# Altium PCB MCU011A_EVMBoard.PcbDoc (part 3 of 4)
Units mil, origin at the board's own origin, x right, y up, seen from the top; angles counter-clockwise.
Board outline 10115 x 9285 mil, 4 copper layers (Top Layer, GND, PWR, Bottom Layer), stack 61.2 mil thick; 438 components, 207 nets, 1196 pads, 248 vias.
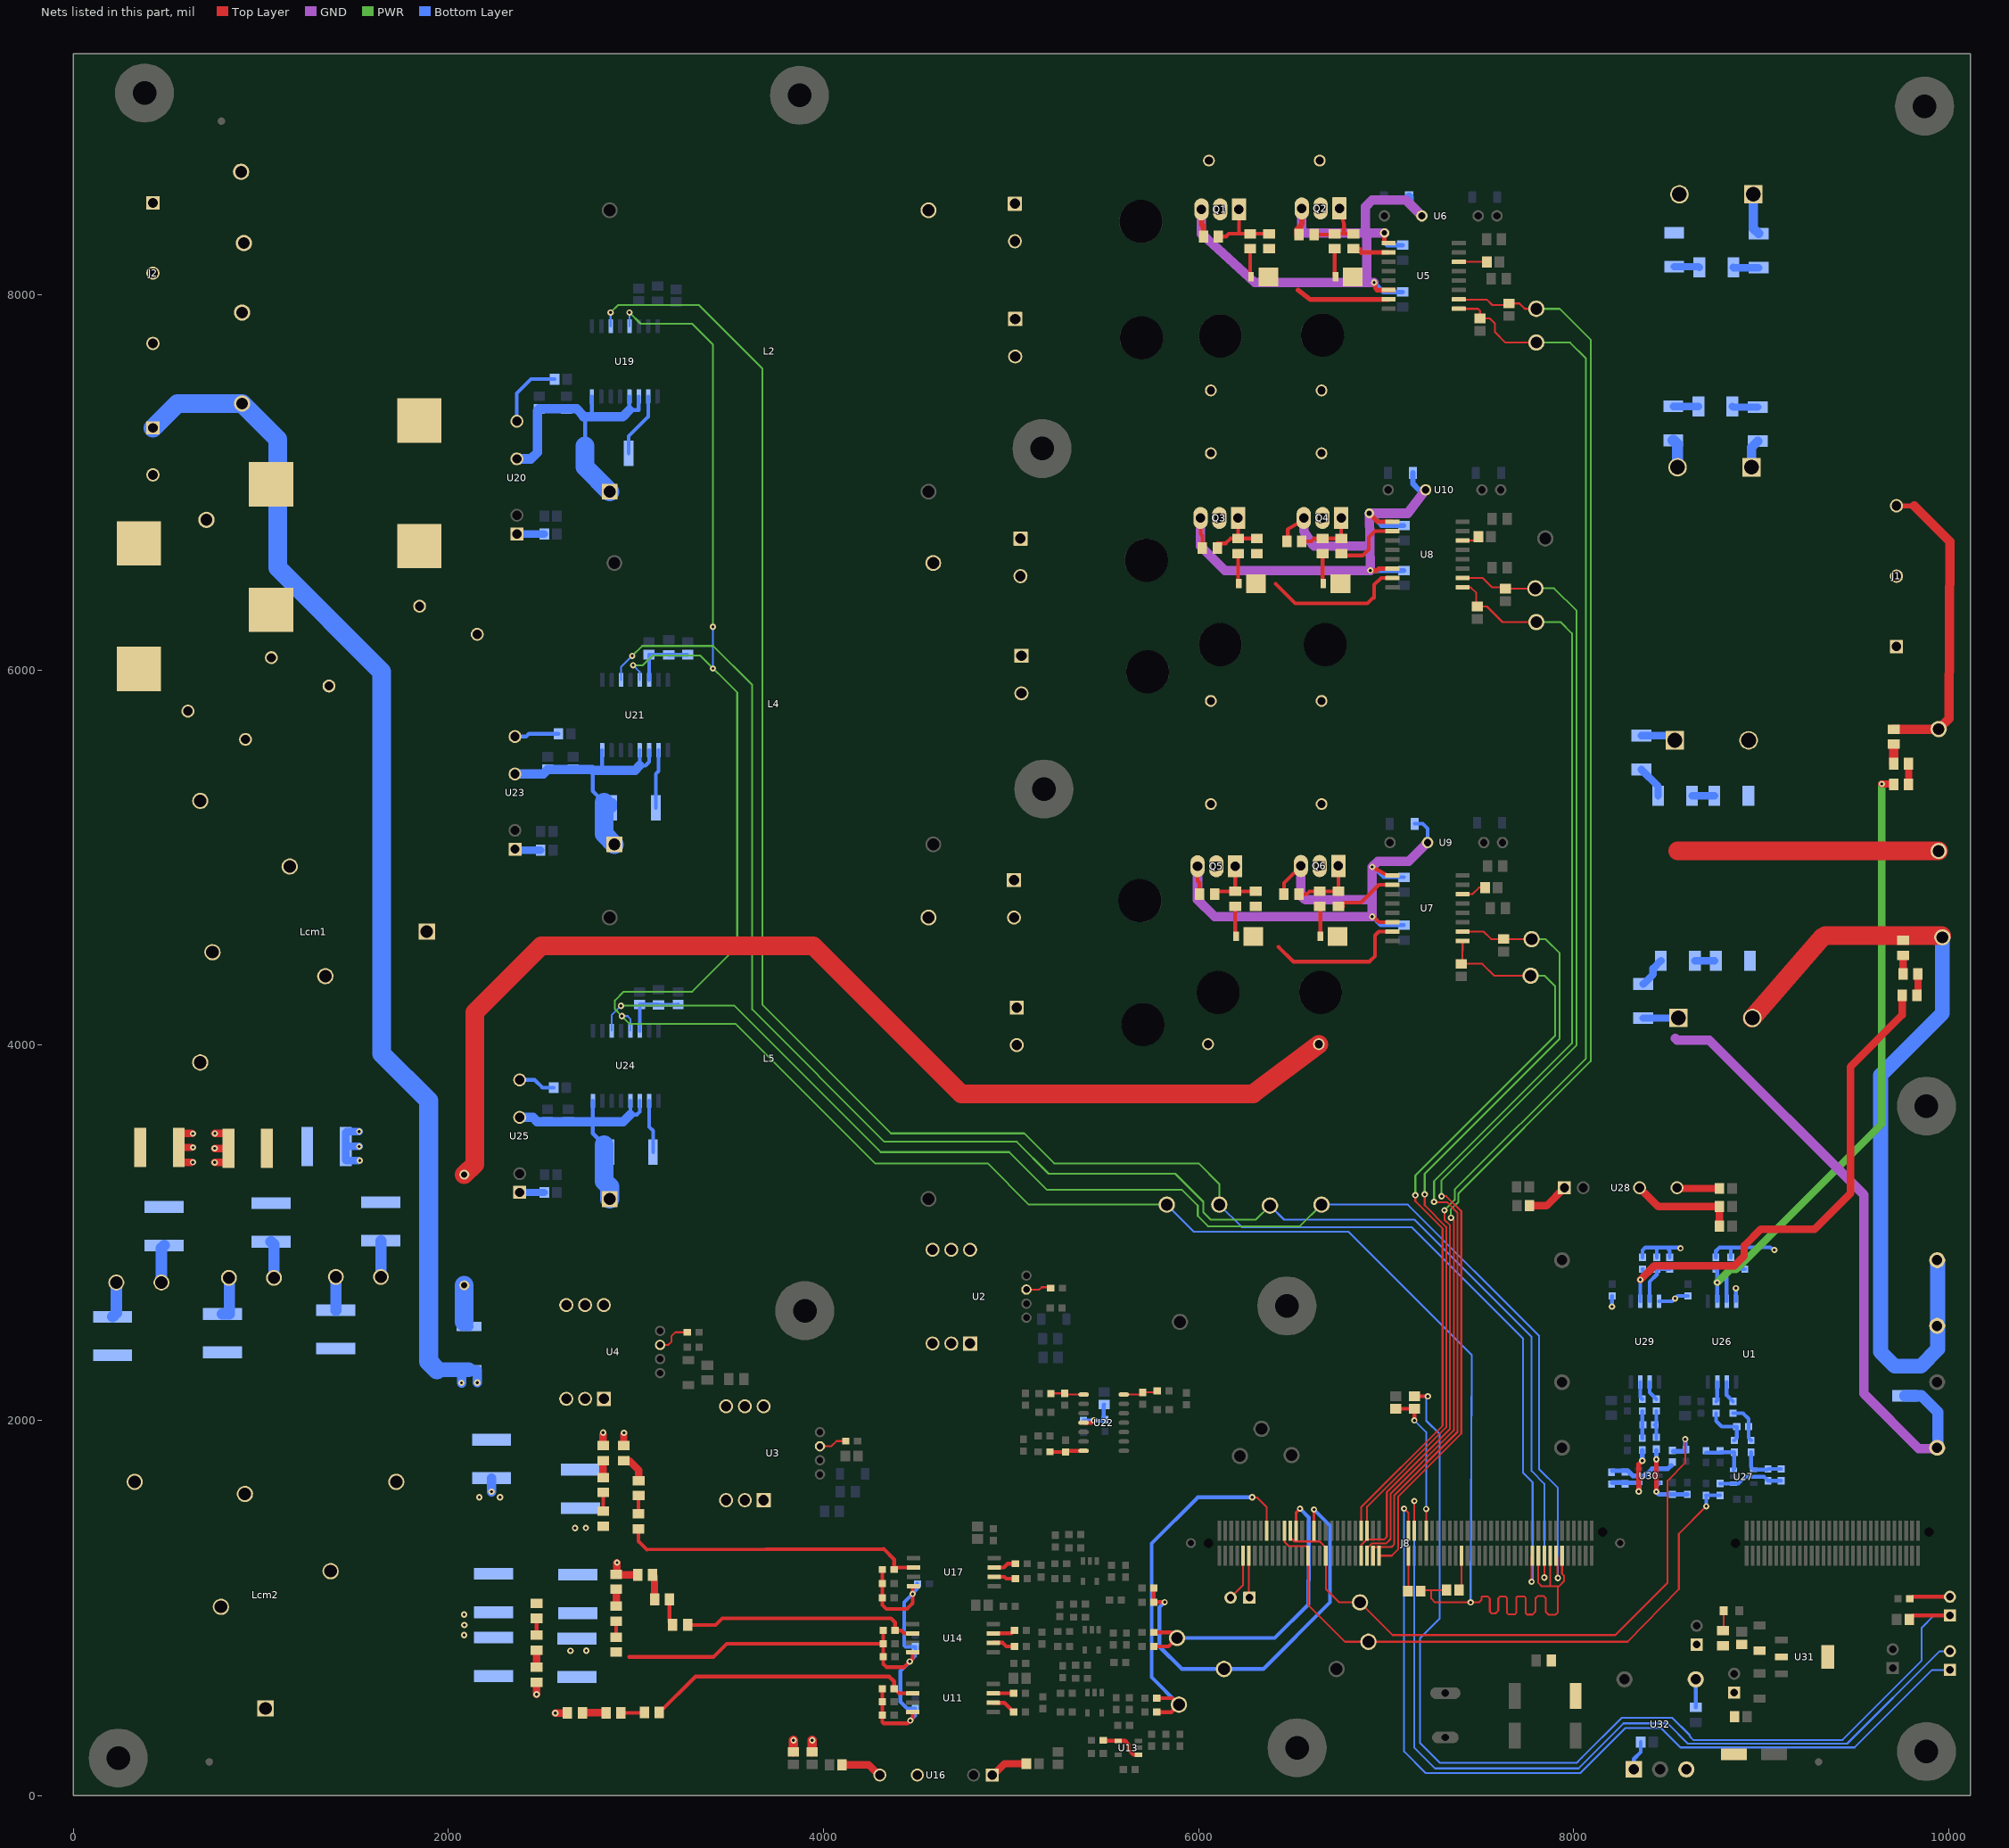
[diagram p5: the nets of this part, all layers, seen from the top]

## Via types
v1: diameter 34, hole 16, Top Layer to Bottom Layer, 243 vias
v2: diameter 50, hole 28, Top Layer to Bottom Layer, 5 vias

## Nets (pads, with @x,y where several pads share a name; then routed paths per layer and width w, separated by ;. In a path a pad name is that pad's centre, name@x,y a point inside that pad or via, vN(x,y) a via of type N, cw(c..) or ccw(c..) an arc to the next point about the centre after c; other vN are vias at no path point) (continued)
NetC67_2: C67.2 C68.1 L12.1 U21.14 | length 336.8
  Bottom Layer w20: U21.14@3070,5946.69 C67.2@3070,6081.54 C68.1@3173.46,6081.54 ; C68.1@3175,6080 L12.1@3273.46,6080
NetC69_2: C69.2 C70.1 L13.1 U22.4 | length 252.5
  Top Layer w20: U22.4@5386.4,1987.74 5428.64,1987.74 v1(5440.45,1999.55)
  Bottom Layer w20: C69.2@5385.96,1999.23 5440.14,1999.23 v1(5440.45,1999.55) 5493.68,1999.55 5493.68,2081.99 L13.1@5495.96,2084.27
NetC76_1: C76.1 C77.2 L16.1 U24.14 | length 343.6
  Bottom Layer w20: U24.14@3020,4077.01 C77.2@3020,4216.54 C76.1@3118.46,4216.54 ; C76.1@3120,4215 3223.46,4215 L16.1@3225,4216.54
NetC82_1: C82.1 R96.1 R99.2 U27.4 | length 246.5
  Bottom Layer w20: R99.2@8945,1830.45 8945,1751.54 U27.4@8959.13,1737.4 9030.9,1737.4 C82.1@9035,1741.5 R96.1@9105,1741.5
NetC82_2: C82.2 R96.2 R101.1 U27.1 | length 349.7
  Bottom Layer w20: R101.1@8780,1663.45 8780.84,1662.6 U27.1@8850.86,1662.6 8877.6,1662.6 8915,1700 9013.51,1700 C82.2@9035,1678.51 R96.2@9105,1678.51
NetC87_1: C87.1 R98.2 R99.1 | length 216.4
  Bottom Layer w20: R98.2@8848.09,2038.27 8901.73,2038.27 8931.5,2008.5 C87.1@8931.5,1966.95 8931.5,1906.95 R99.1@8945,1893.45
NetC87_2: C87.2 R102.2 R103.1 | length 243.3
  Bottom Layer w20: R102.2@8758.09,2038.27 8758.09,1996.91 8788.05,1966.95 C87.2@8868.5,1966.95 8868.5,1906.95 R103.1@8855,1893.45
NetC89_1: C89.1 R103.2 R105.2 U27.3 | length 245.6
  Bottom Layer w20: R105.2@8705,1828.45 8780,1828.45 8782.01,1830.45 R103.2@8855,1830.45 8855,1741.54 U27.3@8850.86,1737.4
NetC90_2: C90.2 R104.1 U26.3 | length 256.2
  Bottom Layer w20: U26.3@8814.41,2634.57 8814.41,2784.21 R104.1@8836.7,2806.5 C90.2@8911.7,2806.5
NetC94_1: C94.1 R108.1 R111.2 U30.4 | length 415.5
  Top Layer w25: v1(8345.86,1620.86) 8345.86,1765.86 v1(8365,1785)
  Bottom Layer w25: R108.1@8205,1668.51 8275,1668.51 8275.9,1667.6 U30.4@8345.86,1667.6 v1(8345.86,1620.86) ; v1(8365,1785) R111.2@8365,1840.45
NetC94_2: C94.2 R108.2 R113.1 U30.1 | length 347.4
  Bottom Layer w25: R108.2@8205,1731.5 8275,1731.5 8287.04,1731.5 8313.53,1705.01 8380.31,1705.01 8417.71,1742.41 U30.1@8454.13,1742.41 8501.96,1742.41 R113.1@8518.9,1759.35
NetC99_1: C99.1 R110.2 R111.1 | length 147
  Bottom Layer w20: R111.1@8365,1903.45 R110.2@8365,2050.45
NetC99_2: C99.2 R114.2 R115.1 | length 154.1
  Bottom Layer w20: R115.1@8440,1903.45 8440,1968.45 C99.2@8431.5,1976.95 8440,1985.45 R114.2@8440,2050.45
NetC101_1: C101.1 R115.2 R117.2 U30.3 | length 444.9
  Top Layer w25: v1(8440,1620) v1@8440,1790
  Bottom Layer w25: v1@8440,1790 R115.2@8440,1840.45 ; U30.3@8454.13,1667.6 8440,1653.47 v1(8440,1620) 8454.55,1605.45 C101.1@8525,1605.45 R117.2@8605,1605.45
  other v1: 8440,1792
NetC102_2: C102.2 R116.1 U29.3 | length 258.2
  Bottom Layer w20: U29.3@8404.41,2634.57 8404.41,2739.41 8443.7,2778.7 R116.1@8443.7,2806.5 ; R116.1@8441.7,2806.5 R116.1@8443.7,2806.5 ; C102.2@8511.7,2806.5 R116.1@8443.7,2806.5
NetC103_2: C103.2 J8.64 R120.2 | length 774.8
  Top Layer w10: J8.64@7212.8,1412.8 v1(7212.8,1527.8)
  Top Layer w20: C103.2@7050,2061.54 R120.2@7150,2061.54 v1(7150,2000)
  Bottom Layer w10: v1(7150,2000) 7212.8,1937.2 v1(7212.8,1527.8)
NetC105_2: C105.2 C106.1 L21.1 U32.1 | length 160.1
  Bottom Layer w20: U32.1@8320,140 8320,195 8356.54,231.54 C105.2@8356.54,285
NetC107_1: C107.1 C108.2 J11.1 U32.3
NetC109_1: C109.1 C110.2 J12.1 R123.2 U31.2 U31.4
NetCm1_1: Cm1.1 Cvn4.2 Cvn5.2 Cvn6.2 RN1.2 | length 301.6
  Bottom Layer w50: RN1.2@2085,2526.14 RN1.2@2110,2501.14 ; v1(2230,1620) Cvn4.2@2230,1692.64
  Bottom Layer w100: RN1.2@2085,2526.14 Cm1.1@2085,2719.72
  other v1: 2084,856 2085,909 2084,965 2165,1590 2275,1590
NetCx1_1: Cx1.1 Lcm2.6 Ldm3.2 | length 190.9
  Bottom Layer w60: Cx1.1@210,2552.36 229.92,2572.28 Ldm3.2@229.92,2735
NetCx1_2: Cx1.2 Cx2.2 Cx3.2
NetCx2_1: Cx2.1 Lcm2.4 Ldm2.2 | length 231
  Bottom Layer w60: Cx2.1@795,2567.36 832.36,2567.36 832.36,2757.56 Ldm2.2@829.92,2760
NetCx3_1: Cx3.1 Lcm2.2 Ldm1.2 | length 177.7
  Bottom Layer w60: Ldm1.2@1399.92,2765 1400,2764.92 Cx3.1@1400,2587.36
NetCx4_1: Cx4.1 Cy1.1 Lcm1.5 Ldm3.1 | length 203.8
  Bottom Layer w60: Ldm3.1@470.08,2735 470.08,2917.72 Cx4.1@485,2932.64
NetCx4_2: Cx4.2 Cx5.2 Cx6.2
NetCx5_1: Cx5.1 Cy2.1 Lcm1.3 Ldm2.1 | length 198.9
  Bottom Layer w60: Cx5.1@1055,2952.64 1070.08,2937.56 Ldm2.1@1070.08,2760
NetCx6_1: Cx6.1 Cy3.1 Lcm1.1 Ldm1.1 | length 555.7
  Bottom Layer w40: v1@1520,3385 1454.72,3385 1452.36,3387.36 Cy3.1@1452.36,3460 ; v1(1525,3460) Cy3.1@1452.36,3460 ; v1(1525,3540) 1458.27,3540 1452.36,3534.09 Cy3.1@1452.36,3460
  Bottom Layer w60: Cx6.1@1640,2957.64 1640,2765.08 Ldm1.1@1640.08,2765
  other v1: 1528,3385
NetD1_2: D1.2 D4.1 L2.3 Q1.2
NetD2_2: D2.2 D5.1 L4.3 Q3.2
NetD3_2: D3.2 D6.1 L5.3 Q5.2
NetD7_1: D7.1 R20.1 U5.15 | length 500
  Top Layer w25: 6530,8025 6595,7975 U5.15@7012.99,7975
NetD7_2: D7.2 R19.2 | length 151.7
  Top Layer w20: R19.2@6275,8245 6275,8099 D7.2@6279,8095
NetD8_1: D8.1 R26.1 U5.10 | length 182
  Top Layer w20: R26.1@6825,8245 6860,8245
  Top Layer w25: 6866,8224 U5.10@7012.99,8225
NetD8_2: D8.2 R25.2 | length 151.7
  Top Layer w20: R25.2@6725,8245 6725,8099 D8.2@6729,8095
NetD9_1: D9.1 R29.1 U7.15 | length 765.9
  Top Layer w20: 6425,4525 6505,4445 6910,4445 6940,4475 6940,4585 6960,4605 U7.15@7027.01,4605
NetD9_2: D9.2 R28.2 | length 161.7
  Top Layer w20: R28.2@6195,4740 6195,4584 D9.2@6199,4580
NetD10_1: D10.1 R35.1 U8.15 | length 744.6
  Top Layer w20: 6410,6460 6515,6355 6900,6355 6930,6385 ; 6935,6385 6935,6450 ; 6935,6455 6972.99,6490 U8.15@7025,6490
NetD10_2: D10.2 R34.2 | length 162.1
  Top Layer w20: R34.2@6210,6620.39 6210,6464 D10.2@6214,6460
NetD11_1: D11.1 R38.1 U7.10 | length 319.4
  Top Layer w20: R38.1@6745,4740 R38.1@6770,4740 ; R38.1@6775,4760 6865,4760 6960,4855 U7.10@7030,4855
NetD11_2: D11.2 R36.2 | length 161.7
  Top Layer w20: R36.2@6645,4740 6649,4736 D11.2@6649,4580
NetD12_1: D12.1 R44.1 U8.10 | length 343.4
  Top Layer w20: R44.1@6760,6620.39 R44.1@6771.75,6620.39 ; R44.1@6765,6610 6824.99,6610.67 6875.67,6610.67 6906.96,6641.96 6906.96,6706.96 6940,6740 U8.10@7005,6740
NetD12_2: D12.2 R43.2 | length 161.9
  Top Layer w20: R43.2@6660.39,6620.39 6660.39,6463.61 D12.2@6664,6460
NetD13_2: D13.2 R123.1 | length 106.5
  Top Layer w10: R123.1@8795,879.68 8798.66,883.35 D13.2@8798.66,984.68
NetJ5_1: J5.1 J8.11 | length 225.2
  Top Layer w10: J8.11@6267.91,1278.94 6267.41,1278.43 6267.41,1057.59 J5.1@6270,1055
NetJ5_2: J5.2 J8.9 | length 251.4
  Top Layer w10: J5.2@6170,1055 6236.42,1121.42 J8.9@6236.42,1278.94
NetJ7_1: J7.1 J8.58 | length 4697.6
  Top Layer w10: v1(7095,1530) 7118.31,1506.69 J8.58@7118.31,1412.8
  Bottom Layer w10: v1(7095,1530) 7095,235 7210,120 8035,120 8275,360 8465,360 8568,257 9497,257 9910,670 J7.1@10010,670
NetJ7_2: J7.2 J8.60 | length 4725.8
  Top Layer w10: J8.60@7149.8,1412.8 v1(7149.8,1569.8)
  Bottom Layer w10: v1(7149.8,1569.8) 7149.8,255.2 7260,145 8025,145 8265,385 8500,385 8608,277 9457,277 9950,770 J7.2@10010,770
NetJ8_57: J8.57 R118.1 | length 162.2
  Top Layer w10: R118.1@7118.31,1116.77 J8.57@7118.31,1278.94
NetJ8_75: J8.75 R121.1 | length 168.7
  Top Layer w10: R121.1@7401.77,1110.24 J8.75@7401.77,1278.94
NetJ9_1: J9.1 R119.1 R120.1 | length 5610.5
  Top Layer w20: R120.1@7150,2128.46 v1@7213.46,2128.46 ; R119.1@9788.46,940 9808.46,960 J9.1@10005,960
  Bottom Layer w10: v1(7222,2128) 7214,2120 7214,2101 7213.46,1997.96 7285,1926.42 7285,945 7180,840 7180,280 7285,175 8015.25,175 8042,201.75 8042,202 8255,415 8525,415 8618,322 8618,315.75 8636.75,297 9432,297 9855,720 9855,895 9920,960 J9.1@10005,960
NetJ9_2: J9.2 R122.2 | length 209.1
  Top Layer w20: R122.2@9800,1050 9810,1060 J9.2@10005,1060
NetL7_2: L7.2 U16.1 | length 208.5
  Top Layer w40: U16.1@4900,105 4965,170 L7.2@5081.54,170
NetL8_1: L8.1 U16.7 | length 226.4
  Top Layer w40: L8.1@4098.46,165 4240,165 U16.7@4300,105
NetL10_2: L10.2 U20.1 | length 146.5
  Bottom Layer w40: U20.1@2365,6725 L10.2@2511.54,6725
NetL11_1: L11.1 U20.7 | length 382.6
  Bottom Layer w20: U20.7@2365,7325 2365,7475 2440,7550 L11.1@2566.54,7550
NetL14_2: L14.2 U23.1 | length 138.6
  Bottom Layer w40: U23.1@2355,5045 2360,5040 L14.2@2491.54,5040
NetL15_1: L15.1 U23.7 | length 237.7
  Bottom Layer w20: U23.7@2355,5645 2415,5645 2430,5660 L15.1@2586.54,5660
NetL17_2: L17.2 U25.1 | length 131.5
  Bottom Layer w40: U25.1@2380,3215 L17.2@2511.54,3215
NetL18_1: L18.1 U25.7 | length 198.8
  Bottom Layer w20: U25.7@2380,3815 2460,3815 2501.54,3773.46 L18.1@2561.59,3773.46
NetL19_2: L19.2 U28.1 | length 226.1
  Top Layer w40: L19.2@7763.46,3144.37 7854.37,3144.37 U28.1@7950,3240
NetL20_1: L20.1 U28.7 | length 228
  Top Layer w40: U28.7@8550,3240 8553.52,3236.48 L20.1@8776.54,3236.48
NetLcm1_2: Lcm1.2 RT1.2
NetLcm1_4: Lcm1.4 RT2.2
NetLcm1_6: Lcm1.6 RT3.2
NetR1_1: R1.1 U2.9 | length 138.3
  Top Layer w10: U2.9@5083.72,2695 U2.9@5081.54,2697.19 5149.98,2697.19 5162.8,2710 5204.33,2710 R1.1@5209.33,2705
NetR3_1: R3.1 R5.2 | length 136.1
  Bottom Layer w40: R5.2@8845.55,7404.68 8849.45,7400.79 R3.1@8980,7400.79
NetR4_1: R4.1 R6.2 | length 134.7
  Bottom Layer w40: R6.2@8850.55,8145 8851.1,8144.45 R4.1@8985,8144.45
NetR5_1: R5.1 R7.2 | length 134.7
  Bottom Layer w40: R7.2@8530,7405.24 8663.9,7405.24 R5.1@8664.45,7404.68
NetR6_1: R6.1 R8.2 | length 136.3
  Bottom Layer w40: R8.2@8535,8149.45 8665,8149.45 R6.1@8669.45,8145
NetR9_1: R9.1 U3.9 | length 149.2
  Top Layer w10: U3.9@3980.83,1862.18 4042.19,1862.18 4070,1890 R9.1@4118.5,1890
NetR11_1: R11.1 R13.2 | length 163.3
  Bottom Layer w40: R11.1@8370,4325.55 8422.56,4378.11 8422.56,4408.66 R13.2@8463.9,4450
NetR12_1: R12.1 R14.2 | length 176.5
  Bottom Layer w40: R12.1@8360,5469.45 8449.45,5380 R14.2@8449.45,5330
NetR13_1: R13.1 R15.2 | length 105.4
  Bottom Layer w40: R13.1@8645,4450 R15.2@8750.36,4449
NetR14_1: R14.1 R16.2 | length 118.9
  Bottom Layer w40: R14.1@8630.55,5330 R16.2@8749.45,5330
NetR17_1: R17.1 U4.9 | length 190.6
  Top Layer w10: U4.9@3128.52,2402.18 3172.18,2402.18 3190,2420 3190,2450 3210,2470 R17.1@3273.5,2470
NetR24_1: R24.1 U5.6 | length 171.5
  Top Layer w10: U5.6@7385.01,8175 7470,8175 7490,8175 R24.1@7556.54,8175
NetR33_1: R33.1 U7.6 | length 134
  Top Layer w10: U7.6@7407.01,4805 7460,4805 7495,4840 R33.1@7526.54,4840
NetR42_1: R42.1 U8.6 | length 99.5
  Top Layer w10: U8.6@7395.47,6690 R42.1@7495,6690
NetR46_1: R46.1 R47.2 | length 125
  Top Layer w40: R46.1@2715,441.46 R47.2@2840,441.46
NetR47_1: R47.1 R49.2 | length 125.6
  Top Layer w20: R47.1@2920,441.46 3043.54,441.46 R49.2@3045,442.91
NetR49_1: R49.1 R52.2 U11.2 | length 1489.8
  Top Layer w20: R49.1@3125,442.91 3317.09,635 4350,635 4376.5,608.5 R52.2@4376.5,570 4401.5,545 U11.2@4475.43,545
NetR50_1: R50.1 U11.6 | length 129.6
  Top Layer w20: U11.6@4904.57,495 4963.5,495 R50.1@5013.5,445
NetR54_1: R54.1 U11.7 | length 108.9
  Top Layer w20: U11.7@4904.57,545 R54.1@5013.5,545
NetR59_1: R59.1 U13.1 U13.4 | length 237.3
  Top Layer w20: R59.1@5491.5,295 5494.09,292.4 U13.4@5570.87,292.4 5607.6,292.4 5625,275 5625,245 5652.4,217.6 U13.1@5679.13,217.6
NetR61_1: R61.1 R62.2 | length 134.1
  Top Layer w40: R61.1@3089,1176.46 3099,1166.46 R62.2@3099,1046.46
NetR62_1: R62.1 R64.2 | length 143.1
  Top Layer w20: R62.1@3179,1046.46 3179,926 R64.2@3195,910
NetR64_1: R64.1 R67.2 U14.2 | length 1273.6
  Top Layer w20: R64.1@3275,910 3425,910 3460,945 4360,945 4381.5,923.5 R67.2@4381.5,880 4415,880 4430,865 U14.2@4475.43,865
NetR65_1: R65.1 U14.6 | length 122.2
  Top Layer w20: U14.6@4904.57,815 4955,815 4975,795 R65.1@5018.5,795
NetR69_1: R69.1 U14.7 | length 120.2
  Top Layer w20: U14.7@4904.57,865 5003.5,865 R69.1@5018.5,880
NetR73_1: R73.1 R74.2 | length 156.5
  Top Layer w40: R73.1@2935,1786 2963,1786 3015,1734 R74.2@3015,1679
NetR74_1: R74.1 R76.2 | length 95
  Top Layer w20: R76.2@3013,1501.45 R74.1@3013,1596.45
NetR76_1: R76.1 R79.2 U17.2 | length 1633.7
  Top Layer w20: R76.1@3013,1421.45 3013,1355.45 3058,1310.45 4320,1315 4376.5,1258.5 R79.2@4376.5,1205 4387.8,1216.3 U17.2@4480.43,1216.3
NetR77_1: R77.1 U17.6 | length 118.1
  Top Layer w20: U17.6@4909.57,1166.3 4965,1166.3 4975,1156.3 R77.1@5023.5,1156.3
NetR81_1: R81.1 U17.7 | length 122.2
  Top Layer w20: U17.7@4909.57,1216.3 4961.3,1216.3 4981.3,1236.3 R81.1@5023.5,1236.3
NetR85_2: R85.2 R87.1 U22.1 | length 177.2
  Top Layer w10: R87.1@5212.46,2142.74 5213.96,2144.23 R85.2@5285.96,2144.23 5292.46,2137.74 U22.1@5386.4,2137.74
NetR86_2: R86.2 R88.1 U22.7 | length 182.2
  Top Layer w20: R88.1@5207.46,1832.74 5208.96,1831.24 R86.2@5290.96,1831.24 5297.46,1837.74 U22.7@5386.4,1837.74
NetR91_2: R91.2 R92.2 U22.14 | length 187.7
  Top Layer w10: U22.14@5600.96,2137.74 5689.47,2137.74 R91.2@5700.96,2149.23 5779,2149.23 R92.2@5782.5,2152.74
NetR94_1: R94.1 R95.2 | length 104
  Top Layer w50: R95.2@9705,5500 R94.1@9705,5604
NetR95_1: R95.1 R97.2 | length 110
  Top Layer w40: R97.2@9785,5390 R95.1@9785,5500
NetR97_1: R97.1 R100.2 U26.2 | length 3284.6
  Top Layer w40: v1(9642,5392) 9703,5392 R97.1@9705,5390
  PWR w40: v1(8764.41,2735) 8833.41,2804 8865,2804 9642,3581 v1(9642,5392)
  Bottom Layer w20: R100.2@8757.29,2806.5 8764.41,2799.39 v1(8764.41,2735) U26.2@8764.41,2634.57 ; R100.2@8764.41,2806.5 R100.2@8764.41,2813.39
NetR98_1: R98.1 U26.6 | length 118.1
  Bottom Layer w20: U26.6@8814.41,2205.43 8814.41,2134.94 R98.1@8848.09,2101.26
NetR102_1: R102.1 U26.7 | length 106.8
  Bottom Layer w20: R102.1@8758.09,2101.26 8764.41,2107.58 U26.7@8764.41,2205.43
NetR106_1: R106.1 R107.2 | length 99
  Top Layer w40: R107.2@9755,4380 R106.1@9755,4479
NetR107_1: R107.1 R109.1 | length 117.1
  Top Layer w40: R109.1@9830,4265 9835,4270 R107.1@9835,4380
NetR109_2: R109.2 R112.2 U29.2 | length 2678
  Top Layer w40: v1(8354.41,2749.41) 8429,2824 8856,2824 8908,2876 8908,2920.43 ; 8910,2932.43 8996.29,3018.71 9283.71,3018.71 9475,3210 9475,3885 9750,4160 R109.2@9750,4265
  Bottom Layer w20: U29.2@8354.41,2634.57 v1(8354.41,2749.41) 8368.7,2763.7 8368.7,2804.5 R112.2@8366.7,2806.5
NetR110_1: R110.1 U29.7 | length 96.4
  Bottom Layer w20: U29.7@8354.41,2205.43 8354.41,2124.04 R110.1@8365,2113.45
NetR114_1: R114.1 U29.6 | length 106.7
  Bottom Layer w20: U29.6@8404.41,2205.43 8404.41,2149.04 R114.1@8440,2113.45
NetR124_2: R124.2 U32.4 | length 150
  Bottom Layer w20: R124.2@8650,470 U32.4@8650,620
NetRT1_1: RT1.1 XF1.1
NetRT2_1: RT2.1 XF2.1
NetRT3_1: RT3.1 XF3.1
NetRvn1_1: Rvn1.1 Rvn4.2 | length 90
  Top Layer w40: Rvn4.2@2825,1696 Rvn1.1@2825,1786
NetRvn2_1: Rvn2.1 Rvn5.2 | length 90
  Top Layer w40: Rvn5.2@2895,1010 Rvn2.1@2895,1100
NetRvn3_1: Rvn3.1 Rvn6.2 | length 90
  Top Layer w40: Rvn3.1@2470,685 Rvn6.2@2470,775
NetRvn4_1: Rvn4.1 Rvn7.2 | length 100
  Top Layer w20: Rvn7.2@2825,1516 Rvn4.1@2825,1616
NetRvn5_1: Rvn5.1 Rvn8.2 | length 85
  Top Layer w20: Rvn8.2@2895,845 Rvn5.1@2895,930
NetRvn6_1: Rvn6.1 Rvn9.2 | length 90
  Top Layer w20: Rvn6.1@2470,855 Rvn9.2@2470,945
NetU2_3: U2.3 U2.5 U2.6
NetU3_3: U3.3 U3.5 U3.6
NetU4_3: U4.3 U4.5 U4.6
PWM1A: J8.49 R22.2 TP1.1 U5.1 | length 7795.3
  Top Layer w10: J8.49@6866.34,1278.94 6866.34,1336.34 6895,1365 6988,1365 7003,1380 7003,1617.85 7340,1954.85 7340,3039.75 7310,3069.75 v1(7310,3120) ; U5.1@7387.01,7925 7490,7925 7500,7915 R22.2@7500,7873.46 7551.54,7873.46 7580,7845 7580,7800 7635,7745 TP1.1@7800,7745
  PWR w10: v1(7310,3120) 7365,3175 7365,3230 8065,3930 8065,7660 7980,7745 TP1.1@7800,7745
PWM1B: J8.51 R23.2 TP2.1 U5.2 | length 7789.4
  Top Layer w10: J8.51@6897.83,1278.94 6897.83,1317.83 6925,1345 7000,1345 7023,1368 7023,1609.57 7360,1946.57 7360,3065 v1(7345,3080) ; U5.2@7414,7974 7536,7974 7565,7945 R23.2@7645,7945 ; R23.2@7655,7953.46 7710,7953.46 7738.46,7925 TP2.1@7800,7925
  PWR w10: v1(7345,3080) 7345,3125 7385,3165 7385,3210 8090,3915 8090,7760 7925,7925 TP2.1@7800,7925
PWM2A: J8.53 R41.2 TP5.1 U8.1 | length 6275.4
  Top Layer w10: J8.53@6929.33,1278.94 6929.33,1310 6944.33,1325 7028,1325 7043,1340 7043,1601.28 7380,1938.28 7380,3106.72 7323.72,3163 7257,3163 v1(7255,3165) ; U8.1@7393.46,6440 7450,6440 7480,6410 R41.2@7480,6345 ; R41.2@7485,6338.46 7536.54,6338.46 7620,6255 TP5.1@7800,6255
  PWR w10: v1(7255,3165) 7255,3275 7990,4010 7990,6195 7930,6255 TP5.1@7800,6255
PWM2B: J8.55 R39.2 TP6.1 U8.2 | length 6253.3
  Top Layer w10: J8.55@6960.83,1278.94 7028.94,1278.94 7063,1313 7063,1593 7400,1930 7400,3115 7320,3195 v1(7295,3195) ; U8.2@7427.01,6490 7515,6490 7565,6440 R39.2@7615,6440 ; R39.2@7635,6433.46 7793.46,6433.46 TP6.1@7795,6435
  PWR w10: v1(7295,3195) 7295,3280 8015,4000 8015,6315 7895,6435 TP6.1@7795,6435
PWM3A: J8.50 R31.2 TP3.1 U7.1 | length 4109.6
  Top Layer w10: J8.50@6866.34,1412.8 6866.34,1537.76 7300,1971.42 7300,3023.18 7155,3168.18 v1(7155,3200) ; R31.2@7400,4433.46 7511.54,4433.46 7575,4370 TP3.1@7770,4370 ; R31.2@7405,4445 U7.1@7407.01,4555
  PWR w10: v1(7155,3200) 7155,3305 7900,4050 7900,4315 7845,4370 TP3.1@7770,4370
PWM3B: J8.52 R32.2 TP4.1 U7.2 | length 4152.6
  Top Layer w10: J8.52@6897.83,1412.8 6897.83,1540.97 7320,1963.14 7320,3031.46 7205,3146.46 v1(7205,3205) ; U7.2@7417.99,4605 7520,4605 7559.14,4565.86 R32.2@7625,4565.86 7774.14,4565.86 TP4.1@7775,4565
  PWR w10: v1(7205,3205) 7205,3315 7925,4035 7925,4490 7850,4565 TP4.1@7775,4565
Q1_GATE: Q1.1 R19.1 R20.2 R21.2 | length 408.3
  Top Layer w20: R21.2@6105,8310 6145,8310 6160,8325 6220,8325 ; Q1.1@6215,8455 6215,8330 6220,8325 ; R20.2@6375,8325 6220,8325
Q1_SOURCE: C8.2 C11.2 C13.2 Q1.3 Q2.3 R21.1 R27.1 U5.9 U5.14 U6.5 | length 3375.6
  Top Layer w25: v1(6935,8065) 6945,8030 ; 6950,8025 U5.14@7012.99,8025 U5.14@7040,8025 ; U5.9@6990,8275 v2(6990,8330)
  Top Layer w30: Q1.3@6015,8455 6015,8377 6025,8367 R21.1@6025,8310 ; R27.1@6535,8345 6550,8381.26 Q2.3@6550,8460
  Top Layer w50: R27.1@6535,8320 R27.1@6535,8345
  GND w50: 6015,8325 Q1.3@6015,8456.84 ; 6020,8320 6300,8065 v1(6935,8065) ; 6550,8330 6890,8330 ; 6550,8345 Q2.3@6550,8461.88 ; 6895,8070 6895,8325 ; v2(6990,8330) 6890,8330 ; U6.5@7190,8420 7105,8505 6925,8505 6890,8470 6890,8330
  Bottom Layer w25: v1(6935,8065) 6986,8014 C8.2@7086.99,8014 ; v2(6990,8330) 6990,8280 7006,8264 C11.2@7086.99,8264
  Bottom Layer w50: C13.2@7121.93,8520 7121.93,8488.07 U6.5@7190,8420
Q2_GATE: Q2.1 R25.1 R26.2 R27.2 | length 350.7
  Top Layer w20: R27.2@6615,8320 6720,8320 R25.1@6725,8325 R26.2@6825,8325 ; Q2.1@6750,8460 6775,8375 6775,8325
Q3_GATE: Q3.1 R34.1 R35.2 R37.2 | length 330.3
  Top Layer w20: R37.2@6100,6675 6144.61,6675 6170,6700.39 R34.1@6210,6700.39 ; Q3.1@6210,6810 R34.1@6210,6700.39 ; R35.2@6310,6700 6309.61,6700.39 R34.1@6210,6700.39
Q3_SOURCE: C17.2 C23.2 C25.2 Q3.3 Q4.3 R37.1 R45.1 U8.9 U8.14 U10.5 | length 3345.6
  Top Layer w20: Q3.3@6010,6810 6025,6795 6010,6780 6010,6725 6020,6715 R37.1@6020,6675 ; R45.1@6475,6680 6475,6750 Q4.3@6560,6800
  Top Layer w25: v2(6910,6835) 6955,6790 U8.9@7032.99,6790 ; v1(6915,6530) 6950,6530 6960,6540 U8.14@7032.99,6540
  GND w50: Q3.3@6010,6810 6010,6660 6140,6530 v1(6915,6530) v2(6910,6835) 7115,6835 U10.5@7210,6960 ; Q4.3@6560,6810 6560,6740 6610,6665 ; 6615,6660 6910,6660
  Bottom Layer w25: v2(6910,6835) 6975,6770 C23.2@7095,6770 ; v1(6915,6530) 7000,6530 C17.2@7095,6530
  Bottom Layer w30: C25.2@7141.93,7050 7141.93,6993.07 7175,6960 U10.5@7210,6960
Q4_GATE: Q4.1 R43.1 R44.2 R45.2 | length 326
  Top Layer w20: R45.2@6550,6685 6600,6685 6615.39,6700.39 R43.1@6660.39,6700.39 R44.2@6760,6700.39 Q4.1@6760,6810
Q5_GATE: Q5.1 R28.1 R29.2 R30.2 | length 359.9
  Top Layer w20: R30.2@6085,4805 6100,4820 R28.1@6195,4820 ; Q5.1@6194,4954 6195,4953 R28.1@6195,4820 ; R29.2@6304.24,4820 R28.1@6195,4820
Q5_SOURCE: C14.2 C20.2 C22.2 Q5.3 Q6.3 R30.1 R40.1 U7.9 U7.14 U9.5 | length 3462.4
  Top Layer w20: Q5.3@5994,4954 6005,4943 5994,4932 5994,4876 5999.87,4870.13 6005,4865 R30.1@6005,4805 ; R40.1@6455,4805 6455,4865 Q6.3@6545,4955 ; v1(6925,4685) 6930,4685 6960,4655 U7.14@7032.99,4655 ; v1(6925,4950) U7.9@7005,4905
  GND w50: Q5.3@5994,4954 5994,4776 6085,4685 v1(6925,4685) 6925,4775 ; Q6.3@6545,4955 6545,4795 6560,4780 ; 6570,4775 6925,4775 ; U9.5@7220,5080 7120,4980 6955,4980 v1(6925,4950) 6925,4775
  Bottom Layer w20: v1(6925,4950) 6930,4950 6985,4895 C20.2@7095,4895 ; C14.2@7095,4640 6975,4640 ; C22.2@7151.93,5180 7195,5180 7220,5155 U9.5@7220,5080 ; 6975,4640 6970,4640 v1(6925,4685) 6930,4685 6975,4640
Q6_GATE: Q6.1 R36.1 R38.2 R40.2 | length 351.2
  Top Layer w20: R40.2@6535,4805 6575,4805 6590,4820 R36.1@6645,4820 R38.2@6745,4820 Q6.1@6745,4955
RSH1_1: RSH1.1 U2.4 U19.2 | length 346
  Bottom Layer w20: RSH1.1@2961.14,7155 2961.14,7246.14 3065,7350 U19.2@3065,7457.99
RSH1_2: C65.2 C66.2 L2.1 RSH1.2 U19.3 U19.4 U19.8 U20.5 | length 1638.8
  Bottom Layer w20: 2720,7350 2728.86,7341.14 RSH1.2@2728.86,7195 ; U19.8@2765,7457.99 2765,7355 2770,7350 ; U19.4@2965,7457.99 2965,7385 3015,7385 U19.3@3015,7457.99
  Bottom Layer w50: U20.5@2365,7125 2440,7125 2475,7160 2475,7381.54 C65.2@2485,7391.54 C66.2@2630,7391.54 2683.46,7391.54 2720,7355 2720,7350 2770,7350 2930,7350 2965,7385
  Bottom Layer w100: RSH1.2@2728.86,7195 RSH1.2@2728.86,7155 2728.86,7081.14 L2.1@2860,6950
RSH2_1: RSH2.1 U3.4 U21.2 | length 313.4
  Bottom Layer w20: RSH2.1@3106.14,5265 3106.14,5446.14 3120,5460 U21.2@3120,5572.68
RSH2_2: C72.2 C73.2 L4.1 RSH2.2 U21.3 U21.4 U21.8 U23.5 | length 1469.9
  Bottom Layer w20: 2770,5465 2770,5355 2830,5295 ; U21.8@2820,5572.68 2820,5470 2825,5465 ; U21.4@3020,5572.68 3020,5490 3050,5490 3070,5510 U21.3@3070,5572.68
  Bottom Layer w50: U23.5@2355,5445 2505,5445 C72.2@2530,5470 C73.2@2665,5470 2765,5470 2770,5465 2825,5465 2995,5465 3020,5490 ; RSH2.2@2873.86,5265 RSH2.2@2873.86,5291.14
  Bottom Layer w100: 2830,5295 2830,5125 L4.1@2885,5070
RSH3_1: RSH3.1 U4.4 U24.2 | length 281.7
  Bottom Layer w20: U24.2@3070,3702.99 3070,3565 3091.14,3543.86 RSH3.1@3091.14,3430
RSH3_2: C80.2 C81.2 L5.1 RSH3.2 U24.3 U24.4 U24.8 U25.5 | length 1384.7
  Bottom Layer w20: U24.8@2770,3702.99 2770,3591.54 2770,3530 2830,3470 ; U24.4@2970,3702.99 2970,3630 3005,3630 3020,3645 U24.3@3020,3702.99
  Bottom Layer w40: 2810,3430 2830,3430 ; L5.1@2858.86,3181.14 L5.1@2860,3180
  Bottom Layer w50: U25.5@2380,3615 2450.25,3615 2473.71,3591.54 C80.2@2528.52,3591.54 C81.2@2638.52,3591.54 2770,3591.54 2931.54,3591.54 2970,3630
  Bottom Layer w100: 2830,3470 2830,3430 2830,3275 2860,3245 L5.1@2860,3180
SD_CLKI: J8.101 J8.105 J8.109 R118.2 R121.2 TP_SD_CLKI1.1 U19.13 U21.13 U24.13 | length 14232.8
  Top Layer w10: R118.2@7170,1095 7183.27,1095 7240,1095 ; R121.2@7320.55,1095 7240,1095 ; J8.101@7811.22,1278.94 7810.72,1278.43 7810.72,1134.28 7829.21,1115.79 7874.21,1115.79 7874.72,1116.29 ; J8.105@7874.21,1278.94 7874.72,1278.43 7874.72,1116.29 ; J8.109@7937.2,1278.94 7937.2,1183.05 7947,1173.25 7947,1142 7920.79,1115.79 7914.98,1115.85 ; 7240,1095 7240,1050 7260,1030 v1(7450,1030) 7494,1030 7509,1045 7509,1058 7513,1062 7540,1062 7552,1050 7552,981 7562,971 7582,971 7597,986 7597,1052 7606,1061 7636,1061 7643,1054 7643,975 7652,966 7685,966 7693,974 7693,1055 7700,1062 7735,1062 7744,1053 7744,972 7751,965 7780,965 7796,981 7796,1052 7807,1063 7840,1063 7851,1052 7851,978 7865,964 7902,964 7914.98,976.98 7914.98,1115.85 ; 7874.72,1116.29 7914.98,1115.85
  PWR w10: v1(2965,7905) 3025,7845 3300,7845 3410,7735 v1(3410,6230) ; v1@2984.75,6025 v1(2985,6025) 3037,6025 3089,6077 3343,6077 3540,5880 3540,4525 3300,4285 2935,4285 2888,4238 2888,4192 v1(2925,4155) 2967,4113 3532,4113 4275,3370 4875,3370 5095,3150 TP_SD_CLKI1.1@5830,3150
  Bottom Layer w10: v1(2925,4155) 2955,4155 2970,4140 U24.13@2970,4077.01 ; U19.13@2965,7832.01 v1(2965,7905) ; v1(2985,6025) 3020,5990 U21.13@3020,5946.69 ; v1@3409,5999 v1@3410,6000 ; v1(3410,6008) v1(3410,6230) ; TP_SD_CLKI1.1@5830,3150 5975,3005 6800,3005 7455,2350 v1(7450,1030)
SD_DATA_I1: J8.99 TP_SD_DATA_1.1 U19.11 | length 10746
  Top Layer w10: v1(7775,1140) 7775,1274.21 J8.99@7779.72,1278.94
  PWR w10: v1(2865,7905) 2905,7945 3335,7945 3675,7605 3675,4215 4360,3530 5070,3530 5230,3370 6000,3370 6110,3260 TP_SD_DATA_1.1@6110,3150
  Bottom Layer w10: U19.11@2865,7832.01 v1(2865,7905) ; TP_SD_DATA_1.1@6110,3150 6230,3030 7135,3030 7730,2435 7730,1720 7780.23,1669.77 7780.23,1145.23 v1(7775,1140)
SD_DATA_I2: J8.103 TP_SD_DATA_2.1 U21.11 | length 9031.4
  Top Layer w10: v1(7842.72,1162.28) J8.103@7842.72,1278.94
  PWR w10: v1(2980,6075) 3033,6128 3412,6128 3620,5920 3620,4190 4325,3485 5030,3485 5200,3315 5875,3315 6025,3165 6025,3109.01 6064.01,3070 6305,3070 TP_SD_DATA_2.1@6380,3145
  Bottom Layer w10: U21.11@2920,5946.69 2920,6015 v1(2980,6075) ; TP_SD_DATA_2.1@6380,3145 6455,3070 7150,3070 7775,2445 7775,1730 7842.72,1662.28 v1(7842.72,1162.28)
SD_DATA_I3: J8.107 TP_SD_DATA_3.1 U24.11 | length 7359.4
  Top Layer w10: J8.107@7905.71,1278.94 7912.36,1272.28 7912.36,1162.64 v1(7915,1160)
  PWR w10: v1(2920,4210) 3525,4210 4305,3430 4990,3430 5190,3230 5910,3230 5995,3145 5995,3090 6050,3035 6540,3035 TP_SD_DATA_3.1@6655,3150
  Bottom Layer w10: U24.11@2870,4077.01 2870,4160 v1(2920,4210) ; TP_SD_DATA_3.1@6655,3150 7115,3150 7815,2450 7815,1740 7915,1640 v1(7915,1160)
V_A: Cvn3.1 Cvn6.1 Lcm2.1 R46.2 Rvn3.2 U2.1 U2.2 | length 130.6
  Top Layer w40: v1(2470,540) Rvn3.2@2470,605 ; v1(2570,440) 2633.54,440 R46.2@2635,441.46
V_B: Cvn2.1 Cvn5.1 Lcm2.3 R61.2 Rvn2.2 U3.1 U3.2 | length 179.1
  Top Layer w40: v1(2899,1242) 2899,1184 Rvn2.2@2895,1180 2898.54,1176.46 R61.2@3009,1176.46
V_BUSMN_FDBK: C100.1 J8.26 J8.37 R113.2 TP_VBUSMN_Fdbk1.1 | length 3439.3
  Top Layer w10: J8.26@6488.39,1412.8 6488.39,1376.61 6510,1355 6645,1355 6677.36,1322.64 J8.37@6677.36,1278.94 6677.87,1278.43 6677.87,1102.13 6750,1030 TP_VBUSMN_Fdbk1.1@6860,1030 7034,856 8221,856 8500,1135 8500,1679 8594,1773 v1(8594,1900)
  Bottom Layer w25: R113.2@8531.56,1835 C100.1@8593.45,1835 ; C100.1@8594,1834.45 v1(8594,1900)
V_BUSPM_FDBK: C88.2 J8.24 J8.31 R101.2 TP_VBUSPM_Fdbk1.1 | length 3313.4
  Top Layer w10: J8.24@6456.89,1412.8 6456.89,1353.98 6480.87,1330 6570,1330 6582.87,1317.13 J8.31@6582.87,1278.94 6582.87,1017.13 6780,820 TP_VBUSPM_Fdbk1.1@6905,820 8287.37,820 8560,1100 8560,1396 v1(8706,1542)
  Bottom Layer w20: v1(8706,1542) 8706,1599.45 C88.2@8705,1600.45 R101.2@8780,1600.45
V_C: Cvn1.1 Cvn4.1 Lcm2.5 R73.2 Rvn1.2 U4.1 U4.2 | length 118
  Top Layer w40: Rvn1.2@2825,1866 v1@2825,1925 ; R73.2@2935,1866 v1@2935,1925
  other v1: 2936,1934 2825,1935
V_EARTH: Cy1.2 Cy2.2 Cy3.2 J3.2 TP_E1.1 | length 709.4
  Top Layer w40: v1@629.09,3375.91 562.36,3375.91 Cy1.2@562.36,3455 ; v1@630,3455 Cy1.2@562.36,3455 ; v1@630,3530 564.72,3530 562.36,3527.64 Cy1.2@562.36,3455 ; v1(754.11,3375) 819.39,3375 821.75,3377.36 Cy2.2@821.75,3450 ; v1(754.11,3450) Cy2.2@821.75,3450 ; v1(755.02,3529.09) 821.75,3529.09 Cy2.2@821.75,3450
  other v1: 638,3376 639,3455 638,3529
V_L1: J2.1 TP_VL1.1 XF1.2
V_L1_FDBK: C33.1 J8.18 R53.2 TP_VL1_Fdbk.1 | length 2049.6
  Top Layer w10: v1(6285,1590) 6310,1590 6362.4,1537.6 J8.18@6362.4,1412.8
  Top Layer w20: C33.1@5776.5,445 5855,445 TP_VL1_Fdbk.1@5895,485 5860,520 R53.2@5776.5,520
  Bottom Layer w20: TP_VL1_Fdbk.1@5895,485 5748.7,631.3 5748.7,1343.7 5995,1590 v1(6285,1590)
V_L2: J2.2 TP_VL2.1 XF2.2
V_L2_FDBK: C45.2 J8.28 R68.2 TP_VL2_Fdbk.1 | length 1708.5
  Top Layer w15: J8.28@6519.88,1412.8 6519.88,1509.88 v1(6540,1530)
  Top Layer w20: C45.2@5761.5,795 5840,795 TP_VL2_Fdbk.1@5885,840 5855,870 R68.2@5761.5,870
  Bottom Layer w20: TP_VL2_Fdbk.1@5885,840 6405,840 6585,1020 6585,1147.67 6587,1149.67 6587,1483 v1(6540,1530)
V_L3: J2.3 TP_VL3.1 XF3.2
V_L3_FDBK: C58.1 J8.34 R80.2 TP_VL3_Fdbk.1 | length 2129
  Top Layer w15: J8.34@6614.37,1412.8 6614.37,1524.37 v1(6615,1525)
  Top Layer w20: R80.2@5761.5,1106.3 C58.1@5761.5,1031.3 v1(5818.7,1031.3)
  Bottom Layer w20: v1(5818.7,1031.3) 5791.02,1003.62 5791.02,793.98 5910,675 TP_VL3_Fdbk.1@6135,675 6345,675 6700,1030 6700,1440 v1(6615,1525)
V_M: C1.1 C83.2 C90.1 C92.2 C93.2 C95.2 C102.1 Cbus1.2 Cbus2.2 Cbus3.2 Cbus4.1 Cbus5.2 Cbus6.1 Cbus7.2 Cbus8.1 Cbus9.1 Cbus10.1 Cm1.2 J1.2 Q2.2 Q4.2 Q6.2 R7.1 R8.1 R11.2 R12.2 R100.1 R104.2 R112.1 R116.2 TP_BUSM1.1 U1.1 U26.4 U28.5 U29.4 | length 12872.3
  Top Layer w40: U28.5@8350,3240 8450,3140 C93.2@8776.54,3140 C92.2@8776.54,3035
  Top Layer w100: Cm1.2@2085,3310.28 2140,3365.28 2140,4175 2495,4530 3945,4530 4735,3740 ; 4745,3740 6290.28,3740 ; 6300,3750 Cbus10.1@6640.28,4005 ; 8555,5035 TP_BUSM1.1@9945,5035
  GND w50: 8542,4036 8551,4027 8722,4027 9546,3203 9546,2143 9839,1850 U1.1@9940,1850
  Bottom Layer w20: v1(8203.7,2606.3) C95.2@8203.7,2663.5 ; R112.1@8366.7,2869.5 8366.7,2906.7 8381.7,2921.7 8441.7,2921.7 ; R116.2@8441.7,2869.5 8441.7,2921.7 ; U29.4@8454.41,2634.57 8524.57,2634.57 v1(8540,2650) 8553.5,2663.5 C83.2@8608.7,2663.5 ; C102.1@8511.7,2869.5 8511.7,2904.3 8494.3,2921.7 ; v1(8569,2917) 8564.3,2921.7 8494.3,2921.7 ; R100.1@8757.29,2869.5 8757.29,2902.29 8776.7,2921.7 8836.7,2921.7 ; R104.2@8836.7,2869.5 8836.7,2921.7 ; U26.4@8864.41,2634.57 v1(8864.41,2704.41) ; C90.1@8911.7,2869.5 8911.7,2904.3 8894.3,2921.7 ; v1(9069,2908) 9045,2923 8894.3,2921.7 ; 8441.7,2921.7 8494.3,2921.7 ; 8836.7,2921.7 8894.3,2921.7
  Bottom Layer w40: R12.2@8360,5650.55 8512.6,5650.55 Cbus8.1@8538.15,5625 ; R11.2@8370,4144.45 8557.6,4144.45 Cbus9.1@8558.15,4145
  Bottom Layer w60: R7.1@8530,7224.13 8553.15,7200.98 Cbus3.2@8553.15,7080 ; C1.1@9765,2131.26 9853.74,2131.26 9940,2045 U1.1@9940,1850
V_N_MEAS: C27.1 C35.1 C40.2 C47.1 C50.1 C54.2 C55.2 C60.1 Cvn1.2 Cvn2.2 Cvn3.2 J3.1 R52.1 R56.2 R67.1 R71.2 R79.1 R83.2 RN1.1 Rvn7.1 Rvn8.1 Rvn9.1 TP_N1.1 U11.4 U14.4 U16.5 U17.4 | length 10166.9
  Top Layer w20: Rvn7.1@2824,1435 Rvn7.1@2825,1436 ; 2964,739 3413,739 3484,810 R71.2@4318.5,810 ; R52.1@4313.5,570 R56.2@4313.5,500 C35.1@4313.5,430 4313.5,391.81 4320.31,385 4448.08,385 v1(4462.93,399.84) 4475.43,412.35 U11.4@4475.43,440 ; R79.1@4313.5,1205 R83.2@4313.5,1130 C60.1@4313.5,1055 4313.5,1016.5 4335,995 4445,995 4475,1025 v1(4475,1075) 4475,1110.87 U17.4@4480.43,1116.3 ; R67.1@4318.5,880 R71.2@4318.5,810 ; U14.4@4475.43,765 4475.43,730.43 v1(4460,715) 4430,685 4335,685 4318.5,701.5 C47.1@4318.5,740 R71.2@4318.5,810
  Top Layer w50: C54.2@3840,233.46 v1(3840,295) ; C55.2@3940,233.46 v1(3940,295)
  Bottom Layer w20: v1(4462.93,399.84) 4490,426.92 C27.1@4490,463.5 4446.5,463.5 4410,500 4410,665 v1(4460,715) 4490,745 C40.2@4490,793.5 4436.5,793.5 4430,800 4430,1030 v1(4475,1075) 4499,1101.73 C50.1@4498.57,1129
  Bottom Layer w50: v1(2070,2200) 2070,2267.72 2071.14,2268.86 RN1.1@2110,2268.86 ; RN1.1@2108.86,2270 RN1.1@2110,2268.86 ; v1(2153.86,2201.14) 2153.86,2268.86 RN1.1@2110,2268.86
  Bottom Layer w80: 1940,2270 RN1.1@2108.86,2270
  Bottom Layer w100: J3.1@425,7290 555,7420 TP_N1.1@900,7420 1090,7230 1090,6545 1645,5990 1645,3955 1895,3705 1895,2315 1940,2270
  other v1: 2651,772 2735,773 2675,1426 2733,1427
VBUSN: C1.2 Cbus4.2 Cbus6.2 Cbus8.2 Cbus9.2 Cbus10.2 D4.2 D5.2 D6.2 J1.1 R15.1 R16.1 R106.2 TP_BUSN1.1 U1.2 U1.4 | length 4380.4
  Top Layer w100: Cbus9.2@8951.85,4145 9325,4575 ; 9340,4585 TP_BUSN1.1@9960,4585
  Bottom Layer w80: U1.2@9940,2850 9940,2500 9940,2380 9848.74,2288.74 C1.2@9765,2288.74 9711.26,2288.74 9635,2365 9635,3840 9965,4170 TP_BUSN1.1@9965,4575
VBUSP: Cbus1.1 Cbus2.1 Cbus3.1 Cbus5.1 Cbus7.1 D1.1 D2.1 D3.1 J1.3 R3.2 R4.2 R94.2 TP_BUSP1.1 | length 1991.3
  Top Layer w25: J1.3@9720.04,6874.8 9815.2,6874.8
  Top Layer w50: R94.2@9705,5684 9944,5684 TP_BUSP1.1@9945,5685 10000,5740 ; 9815.2,6874.8 10005,6685 10000,5750
  Bottom Layer w50: Cbus3.1@8946.85,7080 8946.85,7186.54 R3.2@8980,7219.68 ; Cbus2.1@8956.85,8535 8956.85,8353.7 R4.2@8985,8325.55
pads on no net: FID1.1 FID2.1 FID3.1 FID4.1 FID5.1 FID6.1 H1.1 H2.1 H3.1 H4.1 H5.1 H6.1 H7.1 H8.1 H9.1 H10.1 H11.1 J8.1 J8.2 J8.3 J8.4 J8.5 J8.6 J8.8 J8.12 J8.14 J8.17 J8.23 J8.30 J8.32 J8.33 J8.36 J8.39 J8.40 J8.41 J8.42 J8.43 J8.44 J8.45 J8.54 J8.56 J8.59 J8.61 J8.62 J8.63 J8.66 J8.67 J8.68 J8.69 J8.70 J8.71 J8.72 J8.73 J8.74 J8.76 J8.77 J8.78 J8.79 J8.80 J8.81 J8.82 J8.85 J8.86 J8.87 J8.88 J8.89 J8.90 J8.91 J8.92 J8.93 J8.94 J8.95 J8.96 J8.100 J8.102 J8.104 J8.106 J8.108 J8.110 J8.113 J8.114 J8.115 J8.116 J8.117 J8.118 J8.119 J8.120 J8.181 J8.182 J8.185 J8.186 J10.61 J10.62 J10.121 J10.122 J10.123 J10.124 J10.125 J10.126 J10.127 J10.128 J10.129 J10.130 J10.131 J10.132 J10.133 J10.134 J10.136 J10.137 J10.138 J10.139 J10.140 J10.141 J10.142 J10.143 J10.144 J10.145 J10.146 J10.147 J10.148 J10.149 J10.150 J10.151 J10.152 J10.153 J10.154 J10.155 J10.156 J10.159 J10.160 J10.161 J10.162 J10.163 J10.164 J10.165 J10.166 J10.167 J10.168 J10.169 J10.170 J10.171 J10.172 J10.173 J10.174 J10.175 J10.176 J10.177 J10.178 L2.2 L2.4 L4.2 L4.4 L5.2 L5.4 SH-J1.0 SH-J2.0 U1.3 U1.6 U2.10 U3.10 U4.10 U5.7 U5.12 U5.13 U7.7 U7.12 U7.13 U8.7 U8.12 U8.13 U19.1 U19.5 U19.6 U19.10 U19.12 U19.15 U21.1 U21.5 U21.6 U21.10 U21.12 U21.15 U22.8 U24.1 U24.5 U24.6 U24.10 U24.12 U24.15 U32.5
